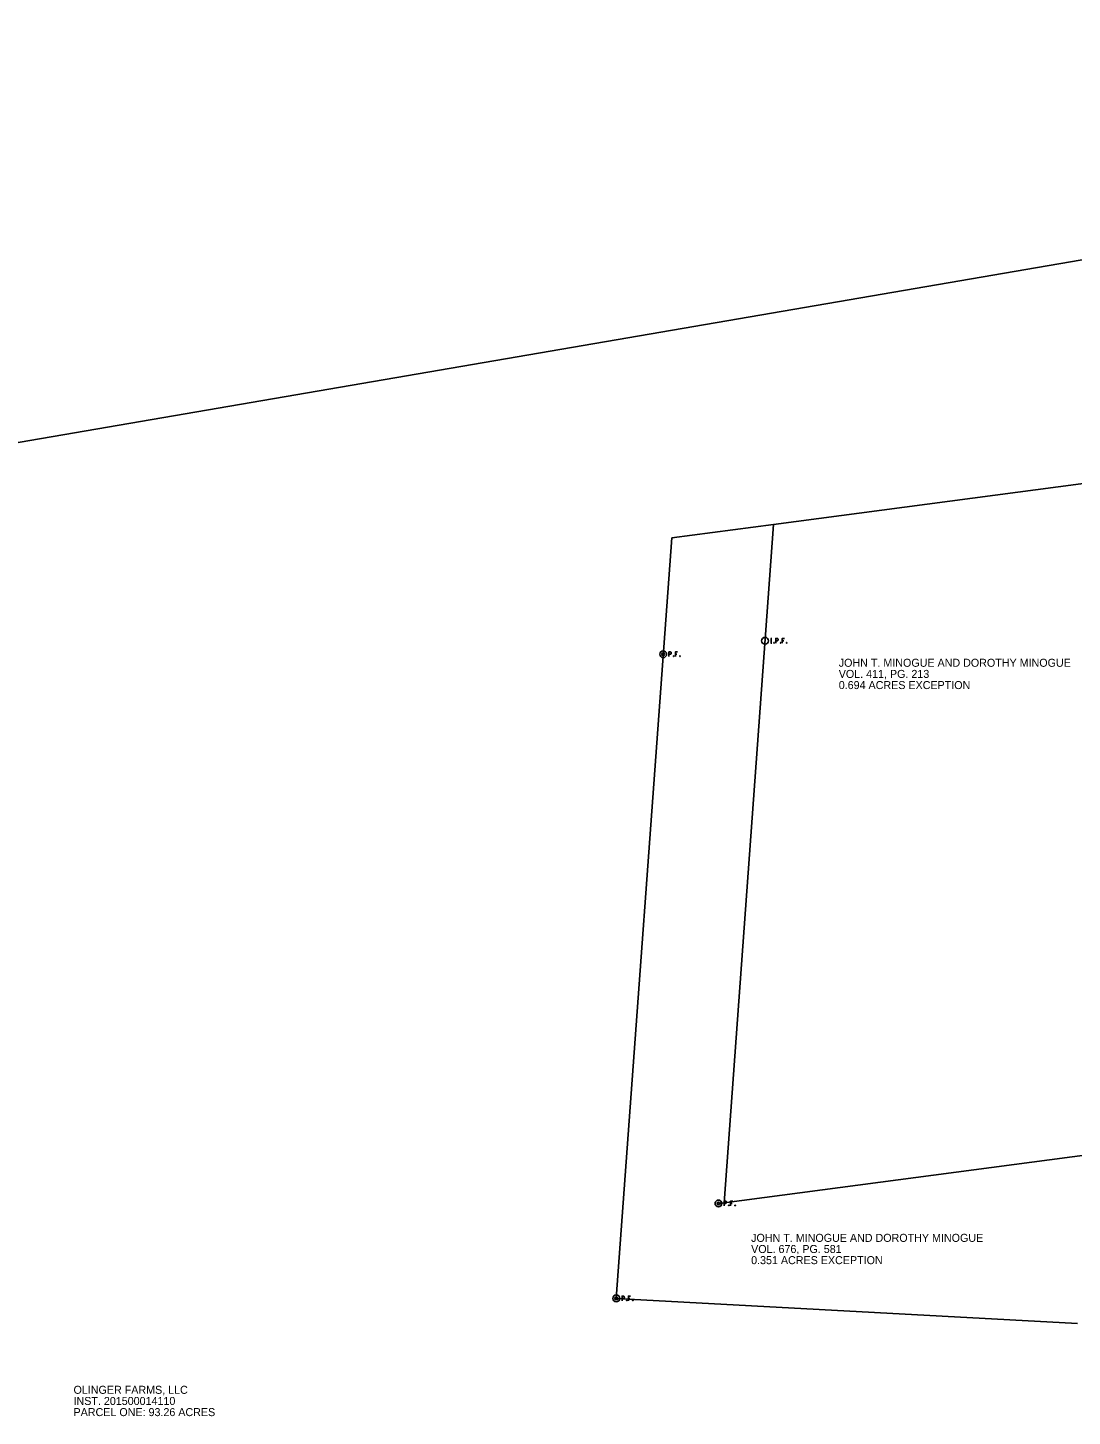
# Model space of a CAD drawing. Extents: x 1532954 to 1577849, y 698998 to 706606.
# Drawn here: x 1537729.3 to 1538094.4, y 701443.9 to 701929.5 of the extents above; entities that cross this region are included whole.
import ezdxf

# ---------------------------------------------------------------- set-up
doc = ezdxf.new("R2010")
doc.units = 0
doc.layers.add('SC_Scratch3', color=7, linetype='Continuous')

msp = doc.modelspace()

# ---------------------------------------------------------------- linework, layer by layer
at = {"layer": 'SC_Scratch3'}
for p, q in [((1538570.16, 701929.51), (1537009.04, 701661.26)), ((1538477.71, 701820.03), (1537989.98, 701755.82)), ((1538117.81, 701772.65), (1537989.97, 701755.82)), ((1537989.98, 701755.82), (1537954.38, 701751.13)), ((1537972.69, 701518.55), (1537989.97, 701755.82)), ((1537989.97, 701755.82), (1537972.69, 701518.55)), ((1537954.38, 701751.13), (1537935, 701485.08)), ((1538100.53, 701535.38), (1537972.69, 701518.55)), ((1537972.69, 701518.55), (1538100.53, 701535.38)), ((1537972.69, 701518.55), (1537970.71, 701518.29)), ((1537935, 701485.08), (1538096.22, 701476.3))]:
    msp.add_line(p, q, dxfattribs=at)
for points in [[(1537989.02, 701715.89), (1537989.37, 701715.89)], [(1537989.02, 701714.29), (1537989.37, 701714.29)], [(1537989.2, 701714.29), (1537989.2, 701715.89)], [(1537990.16, 701714.5), (1537990.21, 701714.5), (1537990.24, 701714.48), (1537990.28, 701714.43), (1537990.28, 701714.37), (1537990.24, 701714.31), (1537990.21, 701714.29), (1537990.16, 701714.29), (1537990.12, 701714.31), (1537990.09, 701714.37), (1537990.09, 701714.43), (1537990.12, 701714.48), (1537990.16, 701714.5)], [(1537990.76, 701714.29), (1537990.76, 701715.89), (1537991.29, 701715.89), (1537991.35, 701715.88), (1537991.42, 701715.85), (1537991.46, 701715.83), (1537991.49, 701715.8), (1537991.53, 701715.74), (1537991.57, 701715.68), (1537991.59, 701715.57), (1537991.59, 701715.42), (1537991.58, 701715.37), (1537991.56, 701715.3), (1537991.51, 701715.21), (1537991.47, 701715.17), (1537991.44, 701715.15), (1537991.38, 701715.12), (1537991.29, 701715.11), (1537990.76, 701715.11)], [(1537992.41, 701714.5), (1537992.46, 701714.5), (1537992.49, 701714.48), (1537992.53, 701714.43), (1537992.53, 701714.37), (1537992.49, 701714.31), (1537992.46, 701714.29), (1537992.41, 701714.29), (1537992.37, 701714.31), (1537992.34, 701714.37), (1537992.34, 701714.43), (1537992.37, 701714.48), (1537992.41, 701714.5)], [(1537993.77, 701715.89), (1537993.01, 701715.89), (1537993.01, 701714.29)], [(1537993.01, 701715.11), (1537993.55, 701715.11)], [(1537994.55, 701714.5), (1537994.61, 701714.5), (1537994.64, 701714.48), (1537994.68, 701714.43), (1537994.68, 701714.37), (1537994.64, 701714.31), (1537994.61, 701714.29), (1537994.55, 701714.29), (1537994.52, 701714.31), (1537994.49, 701714.37), (1537994.49, 701714.43), (1537994.52, 701714.48), (1537994.55, 701714.5)], [(1537953.41, 701709.6), (1537953.41, 701711.2), (1537953.94, 701711.2), (1537954, 701711.19), (1537954.07, 701711.16), (1537954.11, 701711.14), (1537954.14, 701711.11), (1537954.18, 701711.05), (1537954.22, 701710.98), (1537954.24, 701710.88), (1537954.24, 701710.73), (1537954.23, 701710.68), (1537954.21, 701710.61), (1537954.16, 701710.52), (1537954.12, 701710.48), (1537954.08, 701710.45), (1537954.03, 701710.43), (1537953.94, 701710.42), (1537953.41, 701710.42)], [(1537955.05, 701709.81), (1537955.11, 701709.81), (1537955.14, 701709.79), (1537955.18, 701709.74), (1537955.18, 701709.67), (1537955.14, 701709.62), (1537955.11, 701709.6), (1537955.05, 701709.6), (1537955.02, 701709.62), (1537954.99, 701709.67), (1537954.99, 701709.74), (1537955.02, 701709.79), (1537955.05, 701709.81)], [(1537956.42, 701711.2), (1537955.66, 701711.2), (1537955.66, 701709.6)], [(1537955.66, 701710.42), (1537956.2, 701710.42)], [(1537957.2, 701709.81), (1537957.26, 701709.81), (1537957.29, 701709.79), (1537957.33, 701709.74), (1537957.33, 701709.67), (1537957.29, 701709.62), (1537957.26, 701709.6), (1537957.2, 701709.6), (1537957.17, 701709.62), (1537957.14, 701709.67), (1537957.14, 701709.74), (1537957.17, 701709.79), (1537957.2, 701709.81)], [(1537972.7, 701517.49), (1537972.7, 701519.09), (1537973.23, 701519.09), (1537973.29, 701519.08), (1537973.36, 701519.05), (1537973.4, 701519.03), (1537973.43, 701519), (1537973.47, 701518.94), (1537973.51, 701518.88), (1537973.53, 701518.77), (1537973.53, 701518.62), (1537973.52, 701518.57), (1537973.5, 701518.5), (1537973.45, 701518.41), (1537973.41, 701518.37), (1537973.38, 701518.35), (1537973.32, 701518.32), (1537973.23, 701518.31), (1537972.7, 701518.31)], [(1537974.35, 701517.7), (1537974.4, 701517.7), (1537974.43, 701517.68), (1537974.47, 701517.63), (1537974.47, 701517.56), (1537974.43, 701517.51), (1537974.4, 701517.49), (1537974.35, 701517.49), (1537974.31, 701517.51), (1537974.28, 701517.56), (1537974.28, 701517.63), (1537974.31, 701517.68), (1537974.35, 701517.7)], [(1537975.71, 701519.09), (1537974.95, 701519.09), (1537974.95, 701517.49)], [(1537974.95, 701518.31), (1537975.49, 701518.31)], [(1537976.49, 701517.7), (1537976.55, 701517.7), (1537976.58, 701517.68), (1537976.62, 701517.63), (1537976.62, 701517.56), (1537976.58, 701517.51), (1537976.55, 701517.49), (1537976.49, 701517.49), (1537976.46, 701517.51), (1537976.43, 701517.56), (1537976.43, 701517.63), (1537976.46, 701517.68), (1537976.49, 701517.7)], [(1537937, 701484.28), (1537937, 701485.88), (1537937.53, 701485.88), (1537937.58, 701485.86), (1537937.66, 701485.84), (1537937.69, 701485.81), (1537937.72, 701485.79), (1537937.77, 701485.72), (1537937.8, 701485.66), (1537937.82, 701485.56), (1537937.82, 701485.41), (1537937.81, 701485.36), (1537937.79, 701485.28), (1537937.75, 701485.2), (1537937.7, 701485.16), (1537937.67, 701485.13), (1537937.61, 701485.11), (1537937.53, 701485.09), (1537937, 701485.09)], [(1537938.64, 701484.49), (1537938.69, 701484.49), (1537938.73, 701484.46), (1537938.76, 701484.41), (1537938.76, 701484.35), (1537938.73, 701484.3), (1537938.69, 701484.28), (1537938.64, 701484.28), (1537938.61, 701484.3), (1537938.57, 701484.35), (1537938.57, 701484.41), (1537938.61, 701484.46), (1537938.64, 701484.49)], [(1537940.01, 701485.88), (1537939.25, 701485.88), (1537939.25, 701484.28)], [(1537939.25, 701485.09), (1537939.79, 701485.09)], [(1537940.79, 701484.49), (1537940.84, 701484.49), (1537940.88, 701484.46), (1537940.91, 701484.41), (1537940.91, 701484.35), (1537940.88, 701484.3), (1537940.84, 701484.28), (1537940.79, 701484.28), (1537940.76, 701484.3), (1537940.72, 701484.35), (1537940.72, 701484.41), (1537940.76, 701484.46), (1537940.79, 701484.49)]]:
    msp.add_lwpolyline(points, dxfattribs=at)
for centre, radius in [((1537951.41, 701710.4), 1.2), ((1537987.01, 701715.09), 1.2), ((1537951.41, 701710.4), 0.495), ((1537970.71, 701518.29), 1.2), ((1537970.71, 701518.29), 0.495), ((1537935, 701485.08), 1.2), ((1537935, 701485.08), 0.495)]:
    msp.add_circle(centre, radius, dxfattribs=at)

# ---------------------------------------------------------------- texts
for s, p in [('JOHN T. MINOGUE AND DOROTHY MINOGUE', (1538012.77, 701706)), ('VOL. 411, PG. 213', (1538012.77, 701702.1)), ('0.694 ACRES EXCEPTION', (1538012.77, 701698.2)), ('JOHN T. MINOGUE AND DOROTHY MINOGUE', (1537982.14, 701504.85)), ('VOL. 676, PG. 581', (1537982.14, 701500.95)), ('0.351 ACRES EXCEPTION', (1537982.14, 701497.05)), ('OLINGER FARMS, LLC', (1537745.27, 701451.7)), ('INST. 201500014110', (1537745.27, 701447.8)), ('PARCEL ONE: 93.26 ACRES ', (1537745.27, 701443.9))]:
    msp.add_text(s, height=2.8, dxfattribs=at).set_placement(p)

doc.saveas('drawing.dxf')
